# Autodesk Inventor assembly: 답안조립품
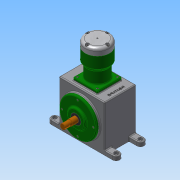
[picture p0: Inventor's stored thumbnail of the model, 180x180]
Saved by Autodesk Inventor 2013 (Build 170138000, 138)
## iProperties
Created: 2016-11
Part Number: 답안조립품
Document SubType Name: Assembly
Designer: Administrator
Mass: 5630 g
Surface Area: 4291.88 cm^2
Volume: 1587.82 cm^3
Author: Administrator
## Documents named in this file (16)
- C:\Users\Administrator\Desktop\361108V1012\답안조립품.iam
- C:\Users\Administrator\Desktop\361108V1012\본체.ipt
- C:\Users\Administrator\Desktop\361108V1012\베어링 20 x 47 x 14.ipt
- C:\Users\Administrator\Desktop\361108V1012\메인크랭크축.ipt
- C:\Users\Administrator\Desktop\361108V1012\베어링 NA 4902.ipt
- C:\Users\Administrator\Desktop\361108V1012\크랭크보조축.ipt
- C:\Users\Administrator\Desktop\361108V1012\앞커버.ipt
- C:\Users\Administrator\Desktop\361108V1012\오일 실 20 35 8.ipt
- C:\Users\Administrator\Desktop\361108V1012\실린더.ipt
- C:\Users\Administrator\Desktop\361108V1012\피스톤.ipt
- C:\Users\Administrator\Desktop\361108V1012\커넥팅로드.ipt
- C:\Users\Administrator\Desktop\361108V1012\피스톤핀.ipt
- C:\Users\Administrator\Desktop\361108V1012\실린더헤드.ipt
- C:\Users\Administrator\Desktop\361108V1012\볼트 M4 x 8.ipt
- C:\Users\Administrator\Desktop\361108V1012\볼트 M5 x 20.ipt
- C:\Users\Administrator\Desktop\361108V1012\가변스프링.ipt
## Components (15 placed, 5 different names)
1. 피스톤:1
2. 피스톤핀:1
3. 가변스프링:1
4. ISO 4762 M4 x 8:5
5. ISO 4762 M4 x 8:6
6. ISO 4762 M4 x 8:7
7. ISO 4762 M4 x 8:8
8. ISO 4762 M4 x 8:1
9. ISO 4762 M4 x 8:2
10. ISO 4762 M4 x 8:3
11. ISO 4762 M4 x 8:4
12. ISO 4762 M5 x 20:1
13. ISO 4762 M5 x 20:2
14. ISO 4762 M5 x 20:3
15. ISO 4762 M5 x 20:4
